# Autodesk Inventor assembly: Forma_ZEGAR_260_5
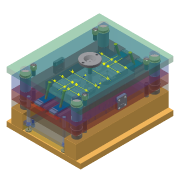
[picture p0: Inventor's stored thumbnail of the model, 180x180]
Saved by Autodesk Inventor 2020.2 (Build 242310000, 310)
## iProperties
Created: 2015-01
Part Number: Forma_ZEGAR_260_5
Document SubType Name: Assembly
Designer: F.Stasiak
Catalog Web Link: www.expertbooks.pl
Manager: www.cadconsulting.pl
Company: Fabian Stasiak CAD Consulting
Author: F.Stasiak
Subject: Zbiór ćwiczeń. Autodesk Inventor 2020. Kurs Professional
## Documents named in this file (11)
- C:\2020_Kurs_Professional\R6 Formy\Forma_ZEGAR_260_5.iam
- C:\2020_Kurs_Professional\R6 Formy\Komponenty\Forma_ZEGAR_260_5_ZEGAR_260_LY.iam
- C:\2020_Kurs_Professional\R6 Formy\Komponenty\Forma_ZEGAR_260_5_RG.ipt
- C:\2020_Kurs_Professional\R6 Formy\Komponenty\Forma_ZEGAR_260_5_CH.ipt
- C:\2020_Kurs_Professional\R6 Formy\Komponenty\MB\DME_E 1\Forma_ZEGAR_260_4_MB.iam
- C:\2020_Kurs_Professional\R6 Formy\Komponenty\Forma_ZEGAR_260_4_Combined CV1.ipt
- C:\2020_Kurs_Professional\R6 Formy\Komponenty\Forma_ZEGAR_260_4_Combined CR1.ipt
- C:\2020_Kurs_Professional\R6 Formy\Komponenty\Wypychacze\DME_AH\Grupa EP2.0\Forma_ZEGAR_260_4_Grupa EP2_EP1.ipt
- C:\2020_Kurs_Professional\R6 Formy\Komponenty\Tuleja wlewowa\DME_AGN\Forma_ZEGAR_260_4_AGN 76-3,5-0.ipt
- C:\2020_Kurs_Professional\R6 Formy\Komponenty\Pierścień centrujący\RABOURDIN_646  typ B\Forma_ZEGAR_260_4_646-90-25-12,5.ipt
- C:\2020_Kurs_Professional\R6 Formy\Komponenty\LS\DME_FW45 1\Forma_ZEGAR_260_4_LS1.iam
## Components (11 placed, 10 different names)
1. Forma_ZEGAR_260_4_ZEGAR_260_LY:1 [sub-assembly] — Równoległy:1, Równoległy:2, Równoległy:3, Równoległy:7, Równoległy:14, Równoległy:15, Równoległy:16, Równoległy:17, Równoległy:18, Równoległy:19, Równoległy:20, Równoległy:21, Równoległy:22, Równoległy:23, Równoległy:24, Równoległy:25, Równoległy:26, Równoległy:27, Równoległy:28, Równoległy:29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
2. Forma_ZEGAR_260_4_RG:1 — Równoległy:4, Równoległy:5, Równoległy:6, Zestawiający:33
3. Forma_ZEGAR_260_4_CH:1
4. Forma_ZEGAR_260_4_MB:1 [sub-assembly] — Równoległy:7, Zestawiający:1, Kąt:1, Równoległy:14, Równoległy:15, Równoległy:16, Równoległy:17, Równoległy:18, Równoległy:19, Równoległy:20, Równoległy:21, Równoległy:22, Równoległy:23, Równoległy:24, Równoległy:25, Równoległy:26, Równoległy:27, Równoległy:28, Równoległy:29, Równoległy:30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
5. Forma_ZEGAR_260_4_Combined CV1:1 — Równoległy:8, Równoległy:9, Równoległy:10
6. Forma_ZEGAR_260_4_Combined CR1:1 — Równoległy:11, Równoległy:12, Równoległy:13
7. Forma_ZEGAR_260_4_Grupa EP2_EP1:1 — Zestawiający:2, Kąt:2, Zestawiający:3
8. Forma_ZEGAR_260_4_AGN 76-3,5-0:1 — Zestawiający:32, Zestawiający:33, Zestawiający:35
9. Forma_ZEGAR_260_4_646-90-25-12,5:1 — Zestawiający:34, Zestawiający:35
10. Forma_ZEGAR_260_4_LS1:1 [sub-assembly] — Zestawiający:36, Równoległy:162, Zestawiający:37, Zestawiający:39, Zestawiający:40, Równoległy:163
11. Forma_ZEGAR_260_4_LS1:2 [sub-assembly] — Zestawiający:38, Zestawiający:39, Zestawiający:40, Równoległy:164
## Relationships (190: Flush 160, Mate 28, Angle 2)
- Równoległy:1 [Flush]: Forma_ZEGAR_260_4_ZEGAR_260_LY:1
- Równoległy:2 [Flush]: Forma_ZEGAR_260_4_ZEGAR_260_LY:1
- Równoległy:3 [Flush]: Forma_ZEGAR_260_4_ZEGAR_260_LY:1
- Równoległy:4 [Flush]: Forma_ZEGAR_260_4_RG:1
- Równoległy:5 [Flush]: Forma_ZEGAR_260_4_RG:1
- Równoległy:6 [Flush]: Forma_ZEGAR_260_4_RG:1
- Równoległy:7 [Flush]: Forma_ZEGAR_260_4_ZEGAR_260_LY:1 ↔ Forma_ZEGAR_260_4_MB:1
- Zestawiający:1 [Mate]: Forma_ZEGAR_260_4_MB:1
- Kąt:1 [Angle]: Forma_ZEGAR_260_4_MB:1
- Równoległy:8 [Flush]: Forma_ZEGAR_260_4_Combined CV1:1
- Równoległy:9 [Flush]: Forma_ZEGAR_260_4_Combined CV1:1
- Równoległy:10 [Flush]: Forma_ZEGAR_260_4_Combined CV1:1
- Równoległy:11 [Flush]: Forma_ZEGAR_260_4_Combined CR1:1
- Równoległy:12 [Flush]: Forma_ZEGAR_260_4_Combined CR1:1
- Równoległy:13 [Flush]: Forma_ZEGAR_260_4_Combined CR1:1
- Równoległy:14 [Flush]: Forma_ZEGAR_260_4_ZEGAR_260_LY:1 ↔ Forma_ZEGAR_260_4_MB:1
- Równoległy:15 [Flush]: Forma_ZEGAR_260_4_ZEGAR_260_LY:1 ↔ Forma_ZEGAR_260_4_MB:1
- Równoległy:16 [Flush]: Forma_ZEGAR_260_4_ZEGAR_260_LY:1 ↔ Forma_ZEGAR_260_4_MB:1
- Równoległy:17 [Flush]: Forma_ZEGAR_260_4_ZEGAR_260_LY:1 ↔ Forma_ZEGAR_260_4_MB:1
- Równoległy:18 [Flush]: Forma_ZEGAR_260_4_ZEGAR_260_LY:1 ↔ Forma_ZEGAR_260_4_MB:1
- Równoległy:19 [Flush]: Forma_ZEGAR_260_4_ZEGAR_260_LY:1 ↔ Forma_ZEGAR_260_4_MB:1
- Równoległy:20 [Flush]: Forma_ZEGAR_260_4_ZEGAR_260_LY:1 ↔ Forma_ZEGAR_260_4_MB:1
- Równoległy:21 [Flush]: Forma_ZEGAR_260_4_ZEGAR_260_LY:1 ↔ Forma_ZEGAR_260_4_MB:1
- Równoległy:22 [Flush]: Forma_ZEGAR_260_4_ZEGAR_260_LY:1 ↔ Forma_ZEGAR_260_4_MB:1
- Równoległy:23 [Flush]: Forma_ZEGAR_260_4_ZEGAR_260_LY:1 ↔ Forma_ZEGAR_260_4_MB:1
- Równoległy:24 [Flush]: Forma_ZEGAR_260_4_ZEGAR_260_LY:1 ↔ Forma_ZEGAR_260_4_MB:1
- Równoległy:25 [Flush]: Forma_ZEGAR_260_4_ZEGAR_260_LY:1 ↔ Forma_ZEGAR_260_4_MB:1
- Równoległy:26 [Flush]: Forma_ZEGAR_260_4_ZEGAR_260_LY:1 ↔ Forma_ZEGAR_260_4_MB:1
- Równoległy:27 [Flush]: Forma_ZEGAR_260_4_ZEGAR_260_LY:1 ↔ Forma_ZEGAR_260_4_MB:1
- Równoległy:28 [Flush]: Forma_ZEGAR_260_4_ZEGAR_260_LY:1 ↔ Forma_ZEGAR_260_4_MB:1
- Równoległy:29 [Flush]: Forma_ZEGAR_260_4_ZEGAR_260_LY:1 ↔ Forma_ZEGAR_260_4_MB:1
- Równoległy:30 [Flush]: Forma_ZEGAR_260_4_ZEGAR_260_LY:1 ↔ Forma_ZEGAR_260_4_MB:1
- Równoległy:31 [Flush]: Forma_ZEGAR_260_4_ZEGAR_260_LY:1 ↔ Forma_ZEGAR_260_4_MB:1
- Równoległy:32 [Flush]: Forma_ZEGAR_260_4_ZEGAR_260_LY:1 ↔ Forma_ZEGAR_260_4_MB:1
- Równoległy:33 [Flush]: Forma_ZEGAR_260_4_ZEGAR_260_LY:1 ↔ Forma_ZEGAR_260_4_MB:1
- Równoległy:34 [Flush]: Forma_ZEGAR_260_4_ZEGAR_260_LY:1 ↔ Forma_ZEGAR_260_4_MB:1
- Równoległy:35 [Flush]: Forma_ZEGAR_260_4_ZEGAR_260_LY:1 ↔ Forma_ZEGAR_260_4_MB:1
- Równoległy:36 [Flush]: Forma_ZEGAR_260_4_ZEGAR_260_LY:1 ↔ Forma_ZEGAR_260_4_MB:1
- Równoległy:37 [Flush]: Forma_ZEGAR_260_4_ZEGAR_260_LY:1 ↔ Forma_ZEGAR_260_4_MB:1
- Równoległy:38 [Flush]: Forma_ZEGAR_260_4_ZEGAR_260_LY:1 ↔ Forma_ZEGAR_260_4_MB:1
- Równoległy:39 [Flush]: Forma_ZEGAR_260_4_ZEGAR_260_LY:1 ↔ Forma_ZEGAR_260_4_MB:1
- Równoległy:40 [Flush]: Forma_ZEGAR_260_4_ZEGAR_260_LY:1 ↔ Forma_ZEGAR_260_4_MB:1
- Równoległy:41 [Flush]: Forma_ZEGAR_260_4_ZEGAR_260_LY:1 ↔ Forma_ZEGAR_260_4_MB:1
- Równoległy:42 [Flush]: Forma_ZEGAR_260_4_ZEGAR_260_LY:1 ↔ Forma_ZEGAR_260_4_MB:1
- Równoległy:43 [Flush]: Forma_ZEGAR_260_4_ZEGAR_260_LY:1 ↔ Forma_ZEGAR_260_4_MB:1
- Równoległy:44 [Flush]: Forma_ZEGAR_260_4_ZEGAR_260_LY:1 ↔ Forma_ZEGAR_260_4_MB:1
- Równoległy:45 [Flush]: Forma_ZEGAR_260_4_ZEGAR_260_LY:1 ↔ Forma_ZEGAR_260_4_MB:1
- Równoległy:46 [Flush]: Forma_ZEGAR_260_4_ZEGAR_260_LY:1 ↔ Forma_ZEGAR_260_4_MB:1
- Równoległy:47 [Flush]: Forma_ZEGAR_260_4_ZEGAR_260_LY:1 ↔ Forma_ZEGAR_260_4_MB:1
- Równoległy:48 [Flush]: Forma_ZEGAR_260_4_ZEGAR_260_LY:1 ↔ Forma_ZEGAR_260_4_MB:1
- Równoległy:49 [Flush]: Forma_ZEGAR_260_4_ZEGAR_260_LY:1 ↔ Forma_ZEGAR_260_4_MB:1
- Równoległy:50 [Flush]: Forma_ZEGAR_260_4_ZEGAR_260_LY:1 ↔ Forma_ZEGAR_260_4_MB:1
- Równoległy:51 [Flush]: Forma_ZEGAR_260_4_ZEGAR_260_LY:1 ↔ Forma_ZEGAR_260_4_MB:1
- Równoległy:52 [Flush]: Forma_ZEGAR_260_4_ZEGAR_260_LY:1 ↔ Forma_ZEGAR_260_4_MB:1
- Równoległy:53 [Flush]: Forma_ZEGAR_260_4_ZEGAR_260_LY:1 ↔ Forma_ZEGAR_260_4_MB:1
- Równoległy:54 [Flush]: Forma_ZEGAR_260_4_ZEGAR_260_LY:1 ↔ Forma_ZEGAR_260_4_MB:1
- Równoległy:55 [Flush]: Forma_ZEGAR_260_4_ZEGAR_260_LY:1 ↔ Forma_ZEGAR_260_4_MB:1
- Równoległy:56 [Flush]: Forma_ZEGAR_260_4_ZEGAR_260_LY:1 ↔ Forma_ZEGAR_260_4_MB:1
- Równoległy:57 [Flush]: Forma_ZEGAR_260_4_ZEGAR_260_LY:1 ↔ Forma_ZEGAR_260_4_MB:1
- Równoległy:58 [Flush]: Forma_ZEGAR_260_4_ZEGAR_260_LY:1 ↔ Forma_ZEGAR_260_4_MB:1
- Równoległy:59 [Flush]: Forma_ZEGAR_260_4_ZEGAR_260_LY:1 ↔ Forma_ZEGAR_260_4_MB:1
- Równoległy:60 [Flush]: Forma_ZEGAR_260_4_ZEGAR_260_LY:1 ↔ Forma_ZEGAR_260_4_MB:1
- Równoległy:61 [Flush]: Forma_ZEGAR_260_4_ZEGAR_260_LY:1 ↔ Forma_ZEGAR_260_4_MB:1
- Równoległy:62 [Flush]: Forma_ZEGAR_260_4_ZEGAR_260_LY:1 ↔ Forma_ZEGAR_260_4_MB:1
- Równoległy:63 [Flush]: Forma_ZEGAR_260_4_ZEGAR_260_LY:1 ↔ Forma_ZEGAR_260_4_MB:1
- Równoległy:64 [Flush]: Forma_ZEGAR_260_4_ZEGAR_260_LY:1 ↔ Forma_ZEGAR_260_4_MB:1
- Równoległy:65 [Flush]: Forma_ZEGAR_260_4_ZEGAR_260_LY:1 ↔ Forma_ZEGAR_260_4_MB:1
- Równoległy:66 [Flush]: Forma_ZEGAR_260_4_ZEGAR_260_LY:1 ↔ Forma_ZEGAR_260_4_MB:1
- Równoległy:67 [Flush]: Forma_ZEGAR_260_4_ZEGAR_260_LY:1 ↔ Forma_ZEGAR_260_4_MB:1
- Równoległy:68 [Flush]: Forma_ZEGAR_260_4_ZEGAR_260_LY:1 ↔ Forma_ZEGAR_260_4_MB:1
- Równoległy:69 [Flush]: Forma_ZEGAR_260_4_ZEGAR_260_LY:1 ↔ Forma_ZEGAR_260_4_MB:1
- Równoległy:70 [Flush]: Forma_ZEGAR_260_4_ZEGAR_260_LY:1 ↔ Forma_ZEGAR_260_4_MB:1
- Równoległy:71 [Flush]: Forma_ZEGAR_260_4_ZEGAR_260_LY:1 ↔ Forma_ZEGAR_260_4_MB:1
- Równoległy:72 [Flush]: Forma_ZEGAR_260_4_ZEGAR_260_LY:1 ↔ Forma_ZEGAR_260_4_MB:1
- Równoległy:73 [Flush]: Forma_ZEGAR_260_4_ZEGAR_260_LY:1 ↔ Forma_ZEGAR_260_4_MB:1
- Równoległy:74 [Flush]: Forma_ZEGAR_260_4_ZEGAR_260_LY:1 ↔ Forma_ZEGAR_260_4_MB:1
- Równoległy:75 [Flush]: Forma_ZEGAR_260_4_ZEGAR_260_LY:1 ↔ Forma_ZEGAR_260_4_MB:1
- Równoległy:76 [Flush]: Forma_ZEGAR_260_4_ZEGAR_260_LY:1 ↔ Forma_ZEGAR_260_4_MB:1
- Równoległy:77 [Flush]: Forma_ZEGAR_260_4_ZEGAR_260_LY:1 ↔ Forma_ZEGAR_260_4_MB:1
- Równoległy:78 [Flush]: Forma_ZEGAR_260_4_ZEGAR_260_LY:1 ↔ Forma_ZEGAR_260_4_MB:1
- Równoległy:79 [Flush]: Forma_ZEGAR_260_4_ZEGAR_260_LY:1 ↔ Forma_ZEGAR_260_4_MB:1
- Równoległy:80 [Flush]: Forma_ZEGAR_260_4_ZEGAR_260_LY:1 ↔ Forma_ZEGAR_260_4_MB:1
- Równoległy:81 [Flush]: Forma_ZEGAR_260_4_ZEGAR_260_LY:1 ↔ Forma_ZEGAR_260_4_MB:1
- Równoległy:82 [Flush]: Forma_ZEGAR_260_4_ZEGAR_260_LY:1 ↔ Forma_ZEGAR_260_4_MB:1
- Równoległy:83 [Flush]: Forma_ZEGAR_260_4_ZEGAR_260_LY:1 ↔ Forma_ZEGAR_260_4_MB:1
- Równoległy:84 [Flush]: Forma_ZEGAR_260_4_ZEGAR_260_LY:1 ↔ Forma_ZEGAR_260_4_MB:1
- Równoległy:85 [Flush]: Forma_ZEGAR_260_4_ZEGAR_260_LY:1 ↔ Forma_ZEGAR_260_4_MB:1
- Równoległy:86 [Flush]: Forma_ZEGAR_260_4_ZEGAR_260_LY:1 ↔ Forma_ZEGAR_260_4_MB:1
- Równoległy:87 [Flush]: Forma_ZEGAR_260_4_ZEGAR_260_LY:1 ↔ Forma_ZEGAR_260_4_MB:1
- Równoległy:88 [Flush]: Forma_ZEGAR_260_4_ZEGAR_260_LY:1 ↔ Forma_ZEGAR_260_4_MB:1
- Równoległy:89 [Flush]: Forma_ZEGAR_260_4_ZEGAR_260_LY:1 ↔ Forma_ZEGAR_260_4_MB:1
- Równoległy:90 [Flush]: Forma_ZEGAR_260_4_ZEGAR_260_LY:1 ↔ Forma_ZEGAR_260_4_MB:1
- Równoległy:91 [Flush]: Forma_ZEGAR_260_4_ZEGAR_260_LY:1 ↔ Forma_ZEGAR_260_4_MB:1
- Równoległy:92 [Flush]: Forma_ZEGAR_260_4_ZEGAR_260_LY:1 ↔ Forma_ZEGAR_260_4_MB:1
- Równoległy:93 [Flush]: Forma_ZEGAR_260_4_ZEGAR_260_LY:1 ↔ Forma_ZEGAR_260_4_MB:1
- Równoległy:94 [Flush]: Forma_ZEGAR_260_4_ZEGAR_260_LY:1 ↔ Forma_ZEGAR_260_4_MB:1
- Równoległy:95 [Flush]: Forma_ZEGAR_260_4_ZEGAR_260_LY:1 ↔ Forma_ZEGAR_260_4_MB:1
- Równoległy:96 [Flush]: Forma_ZEGAR_260_4_ZEGAR_260_LY:1 ↔ Forma_ZEGAR_260_4_MB:1
- Równoległy:97 [Flush]: Forma_ZEGAR_260_4_ZEGAR_260_LY:1 ↔ Forma_ZEGAR_260_4_MB:1
- Równoległy:98 [Flush]: Forma_ZEGAR_260_4_ZEGAR_260_LY:1 ↔ Forma_ZEGAR_260_4_MB:1
- Równoległy:99 [Flush]: Forma_ZEGAR_260_4_ZEGAR_260_LY:1 ↔ Forma_ZEGAR_260_4_MB:1
- Równoległy:100 [Flush]: Forma_ZEGAR_260_4_ZEGAR_260_LY:1 ↔ Forma_ZEGAR_260_4_MB:1
- Równoległy:101 [Flush]: Forma_ZEGAR_260_4_ZEGAR_260_LY:1 ↔ Forma_ZEGAR_260_4_MB:1
- Równoległy:102 [Flush]: Forma_ZEGAR_260_4_ZEGAR_260_LY:1 ↔ Forma_ZEGAR_260_4_MB:1
- Równoległy:103 [Flush]: Forma_ZEGAR_260_4_ZEGAR_260_LY:1 ↔ Forma_ZEGAR_260_4_MB:1
- Równoległy:104 [Flush]: Forma_ZEGAR_260_4_ZEGAR_260_LY:1 ↔ Forma_ZEGAR_260_4_MB:1
- Równoległy:105 [Flush]: Forma_ZEGAR_260_4_ZEGAR_260_LY:1 ↔ Forma_ZEGAR_260_4_MB:1
- Równoległy:106 [Flush]: Forma_ZEGAR_260_4_ZEGAR_260_LY:1 ↔ Forma_ZEGAR_260_4_MB:1
- Równoległy:107 [Flush]: Forma_ZEGAR_260_4_ZEGAR_260_LY:1 ↔ Forma_ZEGAR_260_4_MB:1
- Równoległy:108 [Flush]: Forma_ZEGAR_260_4_ZEGAR_260_LY:1 ↔ Forma_ZEGAR_260_4_MB:1
- Równoległy:109 [Flush]: Forma_ZEGAR_260_4_ZEGAR_260_LY:1 ↔ Forma_ZEGAR_260_4_MB:1
- Równoległy:110 [Flush]: Forma_ZEGAR_260_4_ZEGAR_260_LY:1 ↔ Forma_ZEGAR_260_4_MB:1
- Równoległy:111 [Flush]: Forma_ZEGAR_260_4_ZEGAR_260_LY:1 ↔ Forma_ZEGAR_260_4_MB:1
- Równoległy:112 [Flush]: Forma_ZEGAR_260_4_ZEGAR_260_LY:1 ↔ Forma_ZEGAR_260_4_MB:1
- Równoległy:113 [Flush]: Forma_ZEGAR_260_4_ZEGAR_260_LY:1 ↔ Forma_ZEGAR_260_4_MB:1
- Równoległy:114 [Flush]: Forma_ZEGAR_260_4_ZEGAR_260_LY:1 ↔ Forma_ZEGAR_260_4_MB:1
- Równoległy:115 [Flush]: Forma_ZEGAR_260_4_ZEGAR_260_LY:1 ↔ Forma_ZEGAR_260_4_MB:1
- Równoległy:116 [Flush]: Forma_ZEGAR_260_4_ZEGAR_260_LY:1 ↔ Forma_ZEGAR_260_4_MB:1
- Równoległy:117 [Flush]: Forma_ZEGAR_260_4_ZEGAR_260_LY:1 ↔ Forma_ZEGAR_260_4_MB:1
- Równoległy:118 [Flush]: Forma_ZEGAR_260_4_ZEGAR_260_LY:1 ↔ Forma_ZEGAR_260_4_MB:1
- Równoległy:119 [Flush]: Forma_ZEGAR_260_4_ZEGAR_260_LY:1 ↔ Forma_ZEGAR_260_4_MB:1
- Równoległy:120 [Flush]: Forma_ZEGAR_260_4_ZEGAR_260_LY:1 ↔ Forma_ZEGAR_260_4_MB:1
- Równoległy:121 [Flush]: Forma_ZEGAR_260_4_ZEGAR_260_LY:1 ↔ Forma_ZEGAR_260_4_MB:1
- Równoległy:122 [Flush]: Forma_ZEGAR_260_4_ZEGAR_260_LY:1 ↔ Forma_ZEGAR_260_4_MB:1
- Równoległy:123 [Flush]: Forma_ZEGAR_260_4_ZEGAR_260_LY:1 ↔ Forma_ZEGAR_260_4_MB:1
- Równoległy:124 [Flush]: Forma_ZEGAR_260_4_ZEGAR_260_LY:1 ↔ Forma_ZEGAR_260_4_MB:1
- Równoległy:125 [Flush]: Forma_ZEGAR_260_4_ZEGAR_260_LY:1 ↔ Forma_ZEGAR_260_4_MB:1
- Równoległy:126 [Flush]: Forma_ZEGAR_260_4_ZEGAR_260_LY:1 ↔ Forma_ZEGAR_260_4_MB:1
- Równoległy:127 [Flush]: Forma_ZEGAR_260_4_ZEGAR_260_LY:1 ↔ Forma_ZEGAR_260_4_MB:1
- Równoległy:128 [Flush]: Forma_ZEGAR_260_4_ZEGAR_260_LY:1 ↔ Forma_ZEGAR_260_4_MB:1
- Równoległy:129 [Flush]: Forma_ZEGAR_260_4_ZEGAR_260_LY:1 ↔ Forma_ZEGAR_260_4_MB:1
- Równoległy:130 [Flush]: Forma_ZEGAR_260_4_ZEGAR_260_LY:1 ↔ Forma_ZEGAR_260_4_MB:1
- Równoległy:131 [Flush]: Forma_ZEGAR_260_4_ZEGAR_260_LY:1 ↔ Forma_ZEGAR_260_4_MB:1
- Równoległy:132 [Flush]: Forma_ZEGAR_260_4_ZEGAR_260_LY:1 ↔ Forma_ZEGAR_260_4_MB:1
- Równoległy:133 [Flush]: Forma_ZEGAR_260_4_ZEGAR_260_LY:1 ↔ Forma_ZEGAR_260_4_MB:1
- Równoległy:134 [Flush]: Forma_ZEGAR_260_4_ZEGAR_260_LY:1 ↔ Forma_ZEGAR_260_4_MB:1
- Równoległy:135 [Flush]: Forma_ZEGAR_260_4_ZEGAR_260_LY:1 ↔ Forma_ZEGAR_260_4_MB:1
- Równoległy:136 [Flush]: Forma_ZEGAR_260_4_ZEGAR_260_LY:1 ↔ Forma_ZEGAR_260_4_MB:1
- Równoległy:137 [Flush]: Forma_ZEGAR_260_4_ZEGAR_260_LY:1 ↔ Forma_ZEGAR_260_4_MB:1
- Równoległy:138 [Flush]: Forma_ZEGAR_260_4_ZEGAR_260_LY:1 ↔ Forma_ZEGAR_260_4_MB:1
- Równoległy:139 [Flush]: Forma_ZEGAR_260_4_ZEGAR_260_LY:1 ↔ Forma_ZEGAR_260_4_MB:1
- Równoległy:140 [Flush]: Forma_ZEGAR_260_4_ZEGAR_260_LY:1 ↔ Forma_ZEGAR_260_4_MB:1
- Równoległy:141 [Flush]: Forma_ZEGAR_260_4_ZEGAR_260_LY:1 ↔ Forma_ZEGAR_260_4_MB:1
- Równoległy:142 [Flush]: Forma_ZEGAR_260_4_ZEGAR_260_LY:1 ↔ Forma_ZEGAR_260_4_MB:1
- Równoległy:143 [Flush]: Forma_ZEGAR_260_4_ZEGAR_260_LY:1 ↔ Forma_ZEGAR_260_4_MB:1
- Równoległy:144 [Flush]: Forma_ZEGAR_260_4_ZEGAR_260_LY:1 ↔ Forma_ZEGAR_260_4_MB:1
- Równoległy:145 [Flush]: Forma_ZEGAR_260_4_ZEGAR_260_LY:1 ↔ Forma_ZEGAR_260_4_MB:1
- Zestawiający:2 [Mate]: Forma_ZEGAR_260_4_Grupa EP2_EP1:1
- Kąt:2 [Angle]: Forma_ZEGAR_260_4_Grupa EP2_EP1:1
- Zestawiający:3 [Mate]: Forma_ZEGAR_260_4_MB:1 ↔ Forma_ZEGAR_260_4_Grupa EP2_EP1:1
- Zestawiający:16 [Mate]: Forma_ZEGAR_260_4_ZEGAR_260_LY:1 ↔ Forma_ZEGAR_260_4_MB:1
- Równoległy:150 [Flush]: Forma_ZEGAR_260_4_ZEGAR_260_LY:1 ↔ Forma_ZEGAR_260_4_MB:1
- Równoległy:151 [Flush]: Forma_ZEGAR_260_4_ZEGAR_260_LY:1 ↔ Forma_ZEGAR_260_4_MB:1
- Zestawiający:17 [Mate]: Forma_ZEGAR_260_4_ZEGAR_260_LY:1 ↔ Forma_ZEGAR_260_4_MB:1
- Równoległy:152 [Flush]: Forma_ZEGAR_260_4_ZEGAR_260_LY:1 ↔ Forma_ZEGAR_260_4_MB:1
- Równoległy:153 [Flush]: Forma_ZEGAR_260_4_ZEGAR_260_LY:1 ↔ Forma_ZEGAR_260_4_MB:1
- Zestawiający:18 [Mate]: Forma_ZEGAR_260_4_ZEGAR_260_LY:1 ↔ Forma_ZEGAR_260_4_MB:1
- Równoległy:154 [Flush]: Forma_ZEGAR_260_4_ZEGAR_260_LY:1 ↔ Forma_ZEGAR_260_4_MB:1
- Równoległy:155 [Flush]: Forma_ZEGAR_260_4_ZEGAR_260_LY:1 ↔ Forma_ZEGAR_260_4_MB:1
- Zestawiający:19 [Mate]: Forma_ZEGAR_260_4_ZEGAR_260_LY:1 ↔ Forma_ZEGAR_260_4_MB:1
- Równoległy:156 [Flush]: Forma_ZEGAR_260_4_ZEGAR_260_LY:1 ↔ Forma_ZEGAR_260_4_MB:1
- Równoległy:157 [Flush]: Forma_ZEGAR_260_4_ZEGAR_260_LY:1 ↔ Forma_ZEGAR_260_4_MB:1
- Zestawiający:20 [Mate]: Forma_ZEGAR_260_4_ZEGAR_260_LY:1 ↔ Forma_ZEGAR_260_4_MB:1
- Równoległy:158 [Flush]: Forma_ZEGAR_260_4_ZEGAR_260_LY:1 ↔ Forma_ZEGAR_260_4_MB:1
- Zestawiający:21 [Mate]: Forma_ZEGAR_260_4_ZEGAR_260_LY:1 ↔ Forma_ZEGAR_260_4_MB:1
- Zestawiający:22 [Mate]: Forma_ZEGAR_260_4_ZEGAR_260_LY:1 ↔ Forma_ZEGAR_260_4_MB:1
- Zestawiający:23 [Mate]: Forma_ZEGAR_260_4_ZEGAR_260_LY:1 ↔ Forma_ZEGAR_260_4_MB:1
- Równoległy:159 [Flush]: Forma_ZEGAR_260_4_ZEGAR_260_LY:1 ↔ Forma_ZEGAR_260_4_MB:1
- Zestawiający:24 [Mate]: Forma_ZEGAR_260_4_ZEGAR_260_LY:1 ↔ Forma_ZEGAR_260_4_MB:1
- Zestawiający:25 [Mate]: Forma_ZEGAR_260_4_ZEGAR_260_LY:1 ↔ Forma_ZEGAR_260_4_MB:1
- Zestawiający:26 [Mate]: Forma_ZEGAR_260_4_ZEGAR_260_LY:1 ↔ Forma_ZEGAR_260_4_MB:1
- Równoległy:160 [Flush]: Forma_ZEGAR_260_4_ZEGAR_260_LY:1 ↔ Forma_ZEGAR_260_4_MB:1
- Zestawiający:27 [Mate]: Forma_ZEGAR_260_4_ZEGAR_260_LY:1 ↔ Forma_ZEGAR_260_4_MB:1
- Zestawiający:28 [Mate]: Forma_ZEGAR_260_4_ZEGAR_260_LY:1 ↔ Forma_ZEGAR_260_4_MB:1
- Zestawiający:29 [Mate]: Forma_ZEGAR_260_4_ZEGAR_260_LY:1 ↔ Forma_ZEGAR_260_4_MB:1
- Równoległy:161 [Flush]: Forma_ZEGAR_260_4_ZEGAR_260_LY:1 ↔ Forma_ZEGAR_260_4_MB:1
- Zestawiający:30 [Mate]: Forma_ZEGAR_260_4_ZEGAR_260_LY:1 ↔ Forma_ZEGAR_260_4_MB:1
- Zestawiający:31 [Mate]: Forma_ZEGAR_260_4_ZEGAR_260_LY:1 ↔ Forma_ZEGAR_260_4_MB:1
- Zestawiający:32 [Mate]: Forma_ZEGAR_260_4_MB:1 ↔ Forma_ZEGAR_260_4_AGN 76-3,5-0:1
- Zestawiający:33 [Mate]: Forma_ZEGAR_260_4_RG:1 ↔ Forma_ZEGAR_260_4_AGN 76-3,5-0:1
- Zestawiający:34 [Mate]: Forma_ZEGAR_260_4_MB:1 ↔ Forma_ZEGAR_260_4_646-90-25-12,5:1
- Zestawiający:35 [Mate]: Forma_ZEGAR_260_4_AGN 76-3,5-0:1 ↔ Forma_ZEGAR_260_4_646-90-25-12,5:1
- Zestawiający:36 [Mate]: Forma_ZEGAR_260_4_MB:1 ↔ Forma_ZEGAR_260_4_LS1:1
- Równoległy:162 [Flush]: Forma_ZEGAR_260_4_MB:1 ↔ Forma_ZEGAR_260_4_LS1:1
- Zestawiający:37 [Mate]: Forma_ZEGAR_260_4_LS1:1
- Zestawiający:38 [Mate]: Forma_ZEGAR_260_4_MB:1 ↔ Forma_ZEGAR_260_4_LS1:2
- Zestawiający:39 [Mate]: Forma_ZEGAR_260_4_LS1:1 ↔ Forma_ZEGAR_260_4_LS1:2
- Zestawiający:40 [Mate]: Forma_ZEGAR_260_4_LS1:1 ↔ Forma_ZEGAR_260_4_LS1:2
- Równoległy:163 [Flush]: Forma_ZEGAR_260_4_MB:1 ↔ Forma_ZEGAR_260_4_LS1:1
- Równoległy:164 [Flush]: Forma_ZEGAR_260_4_MB:1 ↔ Forma_ZEGAR_260_4_LS1:2
